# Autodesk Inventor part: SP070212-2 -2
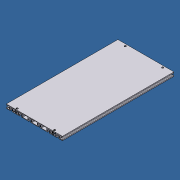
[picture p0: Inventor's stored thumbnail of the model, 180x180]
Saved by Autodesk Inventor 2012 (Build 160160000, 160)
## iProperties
Created: 2012-06
Part Number: SP070212-2 -2
Material: Aluminum-6061
Description: MILL TO SP062512-2-2
Document SubType Name: Modeling
Designer: Administrator
Stock Number: 20.1077 PROFILE 19X270
Density: 2.71 g/cm^3
Mass: 2834.57 g
Surface Area: 6850.66 cm^2
Volume: 1045.97 cm^3
FINISH: CLEAR ANODIZED
Author: Administrator
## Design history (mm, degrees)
sketch "Sketch1"
  geometry: L1 (103.3, 5)-(103.3, -5) reference; L2 (101.3, -7)-(100.091, -7) reference; L3 (98.677, -6.414)-(93.769, -1.506) reference; L4 (91.506, -3.769)-(93.03, -5.293) reference; L5 (92.323, -7)-(87.677, -7) reference; L6 (86.97, -5.293)-(88.494, -3.769) reference; L7 (86.231, -1.506)-(81.323, -6.414) reference; L8 (79.909, -7)-(78.7, -7) reference; L9 (76.7, -5)-(76.7, 5) reference; L10 (78.7, 7)-(79.909, 7) reference; L11 (81.323, 6.414)-(86.231, 1.506) reference; L12 (88.494, 3.769)-(86.97, 5.293) reference; L13 (87.677, 7)-(92.323, 7) reference; L14 (93.03, 5.293)-(91.506, 3.769) reference; L15 (93.769, 1.506)-(98.677, 6.414) reference; L16 (100.091, 7)-(101.3, 7) reference; L17 (-76.7, 5)-(-76.7, -5) reference; L18 (-78.7, -7)-(-79.909, -7) reference; L19 (-81.323, -6.414)-(-86.231, -1.506) reference; L20 (-88.494, -3.769)-(-86.97, -5.293) reference; L21 (-87.677, -7)-(-92.323, -7) reference; L22 (-93.03, -5.293)-(-91.506, -3.769) reference; L23 (-93.769, -1.506)-(-98.677, -6.414) reference; L24 (-100.091, -7)-(-101.3, -7) reference; L25 (-103.3, -5)-(-103.3, 5) reference; L26 (-101.3, 7)-(-100.091, 7) reference; L27 (-98.677, 6.414)-(-93.769, 1.506) reference; L28 (-91.506, 3.769)-(-93.03, 5.293) reference; L29 (-92.323, 7)-(-87.677, 7) reference; L30 (-86.97, 5.293)-(-88.494, 3.769) reference; L31 (-86.231, 1.506)-(-81.323, 6.414) reference; L32 (-79.909, 7)-(-78.7, 7) reference; L33 (33.7, 7)-(56.3, 7) reference; L34 (58.3, 5)-(58.3, -5) reference; L35 (56.3, -7)-(33.7, -7) reference; L36 (31.7, -5)-(31.7, 5) reference; L37 (-11.3, 7)-(11.3, 7) reference; L38 (13.3, 5)-(13.3, -5) reference; L39 (11.3, -7)-(-11.3, -7) reference; L40 (-13.3, -5)-(-13.3, 5) reference; L41 (-56.3, 7)-(-33.7, 7) reference; L42 (-31.7, 5)-(-31.7, -5) reference; L43 (-33.7, -7)-(-56.3, -7) reference; L44 (-58.3, -5)-(-58.3, 5) reference; L45 (135, -4.25)-(130.5, -4.25) reference; L46 (130.5, -4.25)-(130.5, -7) reference; L47 (130.5, -7)-(122.8, -7) reference; L48 (121.8, -6)-(121.8, 6) reference; L49 (122.8, 7)-(130.5, 7) reference; L50 (130.5, 4.25)-(135, 4.25) reference; L51 (135, 4.25)-(135, 9.5) reference; L52 (-135, 9.5)-(135, 9.5) reference; L53 (-135, 4.25)-(-130.5, 4.25) reference; L54 (-130.5, 7)-(-122.8, 7) reference; L55 (-121.8, 6)-(-121.8, -6) reference; L56 (-122.8, -7)-(-130.5, -7) reference; L57 (-130.5, -7)-(-130.5, -4.25) reference; L58 (-130.5, -4.25)-(-135, -4.25) reference; L59 (-135, -9.5)-(-135, -4.25) reference; L60 (-116.6, -9.5)-(-116.6, -5) reference; L61 (-119.3, -5)-(-119.3, 3.5) reference; L62 (-119.3, 3.5)-(-117, 5.8) reference; L63 (-117, 5.8)-(-108, 5.8) reference; L64 (-108, 5.8)-(-105.7, 3.5) reference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; A1 r 2 centre (101.3, 5) between (103.3, 5) and (101.3, 7) reference; A2 r 2 centre (101.3, -5) between (101.3, -7) and (103.3, -5) reference; A3 r 2 centre (100.091, -5) between (98.677, -6.414) and (100.091, -7) reference; A4 r 0.3 centre (93.557, -1.718) between (93.769, -1.506) and (93.287, -1.588) reference; A5 r 3.65 centre (90, 0) between (91.588, -3.287) and (93.287, -1.588) reference; A6 r 0.3 centre (91.718, -3.557) between (91.588, -3.287) and (91.506, -3.769) reference; A7 r 1 centre (92.323, -6) between (92.323, -7) and (93.03, -5.293) reference; A8 r 1 centre (87.677, -6) between (86.97, -5.293) and (87.677, -7) reference; A9 r 0.3 centre (88.282, -3.557) between (88.494, -3.769) and (88.412, -3.287) reference; A10 r 3.65 centre (90, 0) between (86.713, -1.588) and (88.412, -3.287) reference; A11 r 0.3 centre (86.443, -1.718) between (86.713, -1.588) and (86.231, -1.506) reference; A12 r 2 centre (79.909, -5) between (79.909, -7) and (81.323, -6.414) reference; A13 r 2 centre (78.7, -5) between (76.7, -5) and (78.7, -7) reference; A14 r 2 centre (78.7, 5) between (78.7, 7) and (76.7, 5) reference; A15 r 2 centre (79.909, 5) between (81.323, 6.414) and (79.909, 7) reference; A16 r 0.3 centre (86.443, 1.718) between (86.231, 1.506) and (86.713, 1.588) reference; A17 r 3.65 centre (90, 0) between (88.412, 3.287) and (86.713, 1.588) reference; A18 r 0.3 centre (88.282, 3.557) between (88.412, 3.287) and (88.494, 3.769) reference; A19 r 1 centre (87.677, 6) between (87.677, 7) and (86.97, 5.293) reference; A20 r 1 centre (92.323, 6) between (93.03, 5.293) and (92.323, 7) reference; A21 r 0.3 centre (91.718, 3.557) between (91.506, 3.769) and (91.588, 3.287) reference; A22 r 3.65 centre (90, 0) between (93.287, 1.588) and (91.588, 3.287) reference; A23 r 0.3 centre (93.557, 1.718) between (93.287, 1.588) and (93.769, 1.506) reference; A24 r 2 centre (100.091, 5) between (100.091, 7) and (98.677, 6.414) reference; A25 r 2 centre (-78.7, 5) between (-76.7, 5) and (-78.7, 7) reference; A26 r 2 centre (-78.7, -5) between (-78.7, -7) and (-76.7, -5) reference; A27 r 2 centre (-79.909, -5) between (-81.323, -6.414) and (-79.909, -7) reference; A28 r 0.3 centre (-86.443, -1.718) between (-86.231, -1.506) and (-86.713, -1.588) reference; A29 r 3.65 centre (-90, 0) between (-88.412, -3.287) and (-86.713, -1.588) reference; A30 r 0.3 centre (-88.282, -3.557) between (-88.412, -3.287) and (-88.494, -3.769) reference; A31 r 1 centre (-87.677, -6) between (-87.677, -7) and (-86.97, -5.293) reference; A32 r 1 centre (-92.323, -6) between (-93.03, -5.293) and (-92.323, -7) reference; A33 r 0.3 centre (-91.718, -3.557) between (-91.506, -3.769) and (-91.588, -3.287) reference; A34 r 3.65 centre (-90, 0) between (-93.287, -1.588) and (-91.588, -3.287) reference; A35 r 0.3 centre (-93.557, -1.718) between (-93.287, -1.588) and (-93.769, -1.506) reference; A36 r 2 centre (-100.091, -5) between (-100.091, -7) and (-98.677, -6.414) reference; A37 r 2 centre (-101.3, -5) between (-103.3, -5) and (-101.3, -7) reference; A38 r 2 centre (-101.3, 5) between (-101.3, 7) and (-103.3, 5) reference; A39 r 2 centre (-100.091, 5) between (-98.677, 6.414) and (-100.091, 7) reference; A40 r 0.3 centre (-93.557, 1.718) between (-93.769, 1.506) and (-93.287, 1.588) reference; A41 r 3.65 centre (-90, 0) between (-91.588, 3.287) and (-93.287, 1.588) reference; A42 r 0.3 centre (-91.718, 3.557) between (-91.588, 3.287) and (-91.506, 3.769) reference; A43 r 1 centre (-92.323, 6) between (-92.323, 7) and (-93.03, 5.293) reference; A44 r 1 centre (-87.677, 6) between (-86.97, 5.293) and (-87.677, 7) reference; A45 r 0.3 centre (-88.282, 3.557) between (-88.494, 3.769) and (-88.412, 3.287) reference; A46 r 3.65 centre (-90, 0) between (-86.713, 1.588) and (-88.412, 3.287) reference; A47 r 0.3 centre (-86.443, 1.718) between (-86.713, 1.588) and (-86.231, 1.506) reference; A48 r 2 centre (-79.909, 5) between (-79.909, 7) and (-81.323, 6.414) reference; A49 r 2 centre (56.3, 5) between (58.3, 5) and (56.3, 7) reference; A50 r 2 centre (56.3, -5) between (56.3, -7) and (58.3, -5) reference; A51 r 2 centre (33.7, -5) between (31.7, -5) and (33.7, -7) reference; A52 r 2 centre (33.7, 5) between (33.7, 7) and (31.7, 5) reference; A53 r 2 centre (11.3, 5) between (13.3, 5) and (11.3, 7) reference; A54 r 2 centre (11.3, -5) between (11.3, -7) and (13.3, -5) reference; A55 r 2 centre (-11.3, -5) between (-13.3, -5) and (-11.3, -7) reference; A56 r 2 centre (-11.3, 5) between (-11.3, 7) and (-13.3, 5) reference; A57 r 2 centre (-33.7, 5) between (-31.7, 5) and (-33.7, 7) reference; A58 r 2 centre (-33.7, -5) between (-33.7, -7) and (-31.7, -5) reference; A59 r 2 centre (-56.3, -5) between (-58.3, -5) and (-56.3, -7) reference; A60 r 2 centre (-56.3, 5) between (-56.3, 7) and (-58.3, 5) reference; A61 r 1 centre (122.8, -6) between (121.8, -6) and (122.8, -7) reference; A62 r 1 centre (122.8, 6) between (122.8, 7) and (121.8, 6) reference; A63 r 1 centre (-122.8, 6) between (-121.8, 6) and (-122.8, 7) reference; A64 r 1 centre (-122.8, -6) between (-122.8, -7) and (-121.8, -6) reference
  constraints: 248 end point, 128 point on circle, 64 centre point, 44 horizontal, 36 vertical, 360 other
extrude "Extrusion1" new body sketch "Sketch1" stored distance "d0" = 537.6164; taper "d1" = 0 deg
sketch "Sketch3"
  geometry: L1 (-26.6, 0)-(-26.6, -537.616) reference; L2 (243.4, 0)-(243.4, -537.616) reference; L3 (-26.6, -537.616)-(-8.2, -537.616) reference; L4 (225, -537.616)-(243.4, -537.616) reference; L5 (243.4, 0)-(225, 0) reference; L6 (-8.2, 0)-(-26.6, 0) reference; 5 further points
  dimensions: "d9" = 45 distance from line of point (18.4, -528.116) L1; "d10" = 45 distance from line of L2 point (198.4, -528.116); "d11" = 45 distance from line of point (198.4, -7.1) L2; "d12" = 45 distance from line of point (18.4, -7.1) L1; "d13" = 9.5 distance from line of point (18.4, -528.116) L3; "d14" = 9.5 distance from line of L4 point (198.4, -528.116); "d15" = 7.1 distance from line of L5 point (198.4, -7.1); "d16" = 7.1 distance from line of L6 point (18.4, -7.1)
hole "Hole2" sketch "Sketch3" at (18.4, -528.116), (198.4, -528.116), (198.4, -7.1), (18.4, -7.1) diameter "d17" = 8.5; stored, may be unused: countersink angle "d21" = 82 deg, drill point angle "d23" = 118 deg; dims "d18" = 12.7, "d19" = 13, "d20" = 16.6, "d22" = 19.05
body "Solid1"
